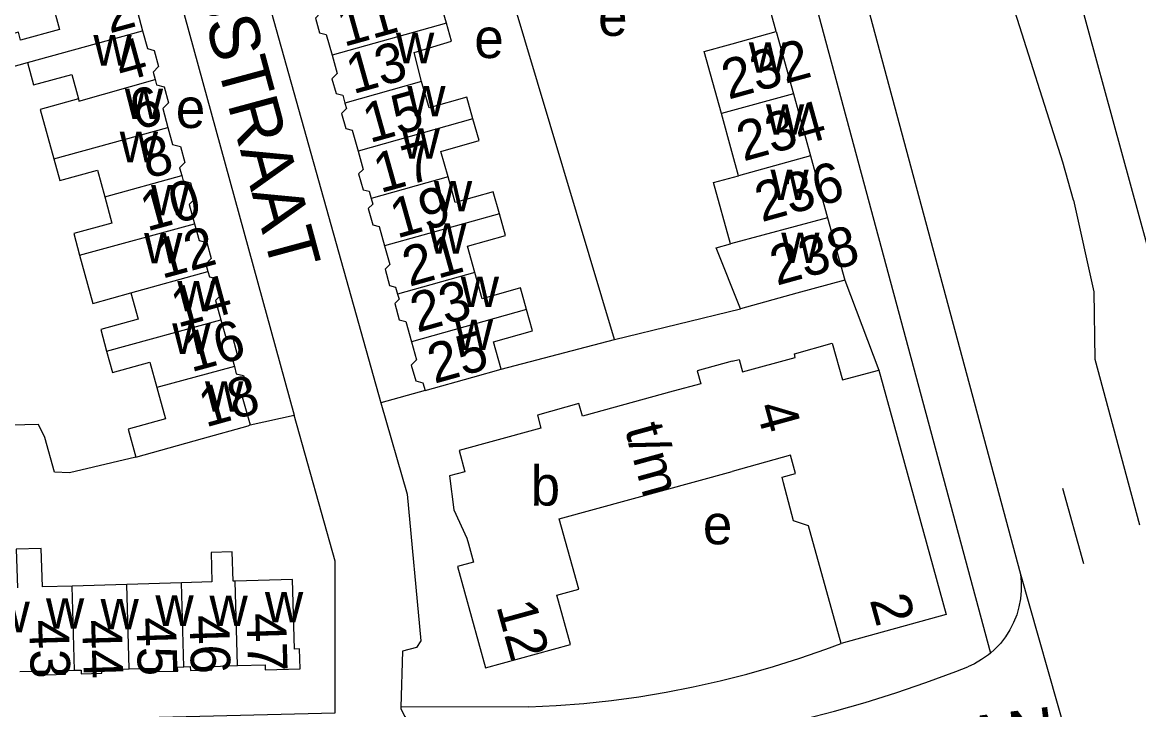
# Model space of a CAD drawing. Extents: x 161258 to 163262, y 380749 to 382054.
# Drawn here: x 162428.3 to 162541.1, y 381217.9 to 381287.2 of the extents above; entities that cross this region are included whole.
import ezdxf

# ---------------------------------------------------------------- set-up
doc = ezdxf.new("R2010")
doc.units = 0
for name, color, linetype in [('BLT_Basislijn', 7, 'Continuous'), ('BLT_Bebouwing', 7, 'Continuous'), ('BLT_Centroide', 7, 'Continuous'), ('BLT_Huisnummer', 7, 'Continuous'), ('BLT_Huisnummer_ tussenligend', 7, 'Continuous'), ('BLT_Huisnummer_reeks', 7, 'Continuous'), ('BLT_Onderverdeling_panden', 7, 'Continuous'), ('BLT_Straatnaam', 7, 'Continuous'), ('BLT_Vlakafsluiter', 7, 'Continuous')]:
    doc.layers.add(name, color=color, linetype=linetype)

msp = doc.modelspace()

# ---------------------------------------------------------------- linework, layer by layer
at = {"layer": 'BLT_Basislijn'}
for p, q in [((162533.38, 381273.13), (162520.81, 381312.73)), ((162488.11, 381255.23), (162472.07, 381308.92)), ((162440.6, 381302.96), (162455.78, 381247.6)), ((162510.03, 381302.47), (162529.11, 381231.56)), ((162505.17, 381301.27), (162526.08, 381223.58)), ((162504.46, 381286.31), (162503, 381291.56)), ((162534.49, 381269.29), (162533.38, 381273.13)), ((162511.37, 381261.23), (162514.81, 381252.15)), ((162488.11, 381255.23), (162500.86, 381258.34)), ((162476.68, 381252.24), (162488.11, 381255.23)), ((162469, 381250.08), (162464.52, 381248.83)), ((162451.33, 381246.61), (162455.78, 381247.6)), ((162533.36, 381240.23), (162535.48, 381232.62)), ((162466.56, 381218.13), (162466.55, 381217.95)), ((162479.46, 381218.15), (162466.56, 381218.13))]:
    msp.add_line(p, q, dxfattribs=at)
for points in [[(162449.41, 381302.85), (162449.7, 381301.79), (162464.52, 381248.83)], [(162534.49, 381269.29), (162536.54, 381260.03), (162536.62, 381253.26), (162541.13, 381236.52)], [(162464.52, 381248.83), (162467.18, 381239.63), (162468.56, 381224.8)], [(162377.35, 381241.55), (162374.93, 381229.15), (162375.77, 381216.02), (162376.51, 381215.48), (162459.91, 381217.55), (162459.91, 381232.85), (162455.78, 381247.6)], [(162439.81, 381243.36), (162433.08, 381241.77), (162431.59, 381241.85), (162430.62, 381245.34), (162429.95, 381246.65), (162408.03, 381246.1)], [(162529.11, 381231.56), (162529.2, 381230.73), (162529.2, 381229.9), (162529.13, 381229.06), (162528.97, 381228.24), (162528.74, 381227.44), (162528.43, 381226.66), (162528.05, 381225.92), (162527.6, 381225.21), (162527.09, 381224.56), (162526.51, 381223.95), (162526.08, 381223.58)], [(162468.56, 381224.8), (162468.14, 381224.14), (162466.73, 381223.78), (162466.56, 381218.13)], [(162479.46, 381218.15), (162482.25, 381218.29), (162485.04, 381218.5), (162487.81, 381218.8), (162490.58, 381219.17), (162493.33, 381219.62), (162496.07, 381220.16), (162498.79, 381220.77), (162501.5, 381221.46), (162504.18, 381222.22), (162506.84, 381223.06), (162509.48, 381223.98), (162511, 381224.55)], [(162526.08, 381223.58), (162525.88, 381223.4), (162525.2, 381222.92), (162524.47, 381222.5), (162523.81, 381222.19)], [(162472.03, 381213.18), (162475.26, 381213.11), (162478.48, 381213.14), (162481.71, 381213.24), (162484.93, 381213.42), (162488.15, 381213.68), (162491.35, 381214.02), (162494.55, 381214.43), (162497.74, 381214.93), (162500.92, 381215.51), (162504.07, 381216.17), (162507.22, 381216.9), (162510.34, 381217.71), (162513.44, 381218.6), (162516.52, 381219.56), (162519.57, 381220.61), (162522.6, 381221.72), (162523.81, 381222.19)], [(162466.55, 381217.95), (162466.97, 381217.19), (162467.45, 381216.47), (162468, 381215.8), (162468.61, 381215.19), (162469.27, 381214.63), (162469.98, 381214.14), (162470.74, 381213.71), (162471.53, 381213.36), (162472.03, 381213.18)]]:
    msp.add_lwpolyline(points, dxfattribs=at)
at = {"layer": 'BLT_Bebouwing'}
for p, q in [((162530.18, 381307.51), (162544.19, 381256.3)), ((162500, 381285.08), (162504.46, 381286.31)), ((162504.46, 381286.31), (162506.19, 381280.04)), ((162506.19, 381280.04), (162507.91, 381273.78)), ((162499.99, 381274.19), (162498.92, 381278.03)), ((162500.66, 381271.76), (162499.99, 381274.19)), ((162507.91, 381273.78), (162509.64, 381267.51)), ((162509.64, 381267.51), (162511.37, 381261.23)), ((162514.81, 381252.15), (162516.39, 381246.43)), ((162505.89, 381243.54), (162500, 381241.92)), ((162482.55, 381237.12), (162500, 381241.92)), ((162438.88, 381230.51), (162433.35, 381230.35)), ((162444.4, 381230.68), (162438.88, 381230.51))]:
    msp.add_line(p, q, dxfattribs=at)
for points in [[(162439.02, 381291.45), (162439.24, 381290.63), (162440.01, 381290.43), (162440.45, 381288.81), (162439.95, 381288.3), (162440.47, 381286.37)], [(162471.15, 381287.17), (162470.53, 381289.36), (162466.7, 381288.28), (162465.97, 381290.88)], [(162431.32, 381289.35), (162432.09, 381286.51), (162428.15, 381285.44), (162427.93, 381286.24), (162424.39, 381285.28), (162425.23, 381282.19), (162428.86, 381283.2)], [(162458.25, 381288.72), (162458.4, 381288.16), (162457.92, 381287.67), (162458.34, 381286.19), (162459.02, 381286.01), (162459.61, 381283.94)], [(162468.65, 381281.27), (162467.9, 381284.2), (162471.67, 381285.33), (162471.15, 381287.17)], [(162440.47, 381286.37), (162440.96, 381284.59), (162441.64, 381284.41), (162442.09, 381282.79), (162441.53, 381282.23), (162441.74, 381281.47)], [(162498.92, 381278.03), (162497.17, 381284.29), (162499.64, 381284.98), (162500, 381285.08)], [(162459.61, 381283.94), (162460.13, 381282.08), (162459.6, 381281.53), (162460.02, 381280.05), (162460.69, 381279.88), (162460.91, 381279.09)], [(162428.86, 381283.2), (162429.47, 381280.94), (162433.32, 381281.99), (162433.99, 381279.51)], [(162441.74, 381281.47), (162441.88, 381280.93), (162442.65, 381280.73), (162443.09, 381279.11), (162442.52, 381278.53), (162443.04, 381276.63)], [(162473.83, 381277.5), (162473.22, 381279.69), (162469.4, 381278.62), (162468.65, 381281.27)], [(162433.99, 381279.51), (162430.15, 381278.46), (162431.51, 381273.48)], [(162460.91, 381279.09), (162461.06, 381278.54), (162460.56, 381278.03), (162460.99, 381276.53), (162461.64, 381276.36), (162462.23, 381274.24)], [(162443.04, 381276.63), (162443.51, 381274.91), (162444.3, 381274.7), (162444.74, 381273.09), (162444.21, 381272.56), (162444.43, 381271.77)], [(162471.33, 381271.64), (162470.6, 381274.22), (162474.45, 381275.3), (162473.83, 381277.5)], [(162431.51, 381273.48), (162432.11, 381271.27), (162435.93, 381272.31), (162436.65, 381269.64)], [(162462.23, 381274.24), (162462.75, 381272.4), (162462.29, 381271.94), (162462.74, 381270.35), (162463.34, 381270.19), (162463.55, 381269.45)], [(162444.43, 381271.77), (162444.57, 381271.24), (162445.3, 381271.05), (162445.75, 381269.42), (162445.19, 381268.85), (162445.71, 381266.92)], [(162476.51, 381267.93), (162475.89, 381270.13), (162472.05, 381269.05), (162471.33, 381271.64)], [(162499.83, 381264.88), (162498.12, 381271.07), (162500.66, 381271.76)], [(162436.65, 381269.64), (162437.38, 381266.97), (162433.53, 381265.92), (162434.12, 381263.75)], [(162463.55, 381269.45), (162463.71, 381268.89), (162463.27, 381268.44), (162463.74, 381266.79), (162464.36, 381266.63), (162464.91, 381264.68)], [(162474.01, 381262), (162473.27, 381264.65), (162477.12, 381265.73), (162476.51, 381267.93)], [(162445.71, 381266.92), (162446.18, 381265.22), (162446.96, 381265.02), (162447.4, 381263.39), (162446.87, 381262.85), (162447.08, 381262.08)], [(162464.91, 381264.68), (162465.44, 381262.81), (162464.96, 381262.32), (162465.42, 381260.67), (162466.03, 381260.52), (162466.22, 381259.81)], [(162500.86, 381258.34), (162498.39, 381264.48), (162499.83, 381264.88)], [(162434.12, 381263.75), (162435.45, 381258.87), (162439.3, 381259.95)], [(162447.08, 381262.08), (162447.22, 381261.55), (162447.96, 381261.36), (162448.4, 381259.74), (162447.85, 381259.18), (162448.38, 381257.22)], [(162479.24, 381258.27), (162478.63, 381260.43), (162474.76, 381259.35), (162474.01, 381262)], [(162511.37, 381261.23), (162506.55, 381259.9), (162500.86, 381258.34)], [(162439.3, 381259.95), (162440.03, 381257.27), (162436.25, 381256.24), (162436.84, 381254.07)], [(162466.22, 381259.81), (162466.37, 381259.3), (162465.93, 381258.86), (162466.39, 381257.21), (162467.05, 381257.04), (162467.62, 381255)], [(162476.68, 381252.24), (162475.91, 381254.99), (162479.84, 381256.1), (162479.24, 381258.27)], [(162448.38, 381257.22), (162448.84, 381255.56), (162449.59, 381255.36), (162450.04, 381253.73), (162449.54, 381253.22), (162449.74, 381252.5)], [(162436.84, 381254.07), (162437.43, 381251.9), (162441.22, 381252.94), (162441.93, 381250.37)], [(162467.62, 381255), (162468.13, 381253.18), (162467.61, 381252.65), (162468.06, 381251.05), (162468.77, 381250.87), (162469, 381250.08)], [(162500, 381253.03), (162500.7, 381253.22), (162501.04, 381251.96), (162506.38, 381253.43), (162506.29, 381253.79), (162510.12, 381254.85), (162511.14, 381251.15)], [(162500, 381253.03), (162496.48, 381252.06), (162496.83, 381250.76), (162494.05, 381250), (162484.88, 381247.48), (162484.52, 381248.76), (162480.34, 381247.61), (162480.7, 381246.29), (162479.95, 381246.09)], [(162449.74, 381252.5), (162449.93, 381251.78), (162450.65, 381251.59), (162451.09, 381250), (162450.54, 381249.43), (162451.33, 381246.61)], [(162469, 381250.08), (162473.81, 381251.43), (162476.68, 381252.24)], [(162511.14, 381251.15), (162514.81, 381252.15)], [(162441.93, 381250.37), (162442.03, 381250), (162442.8, 381247.22), (162439.03, 381246.17), (162439.81, 381243.36)], [(162439.81, 381243.36), (162446.52, 381245.23), (162451.12, 381246.51), (162451.33, 381246.61)], [(162516.39, 381246.43), (162521.6, 381227.48), (162511, 381224.55)], [(162479.95, 381246.09), (162472.43, 381244.02), (162473.02, 381241.89), (162471.45, 381241.46), (162471.91, 381238.05), (162473.21, 381235.17), (162473.37, 381234.59)], [(162505.2, 381240.76), (162505.04, 381241.35), (162506.39, 381241.72), (162505.89, 381243.54)], [(162511, 381224.55), (162507.73, 381236.41), (162506.2, 381236.94), (162505.2, 381240.76)], [(162473.37, 381234.59), (162473.88, 381232.75), (162472.29, 381232.32), (162475.11, 381222.09), (162483.69, 381224.46), (162482.32, 381229.42), (162484.51, 381230.02), (162482.55, 381237.12)], [(162433.35, 381230.35), (162430.36, 381230.26), (162430.25, 381234.15), (162427.71, 381234.07), (162427.83, 381230.18)], [(162449.82, 381230.84), (162449.61, 381230.84), (162449.52, 381233.8), (162447.39, 381233.73), (162447.48, 381230.77), (162444.4, 381230.68)], [(162450.06, 381222.32), (162452.84, 381222.4), (162452.86, 381221.89), (162456.39, 381222), (162456.33, 381224.01), (162455.81, 381223.99), (162455.6, 381231.02), (162449.82, 381230.84)], [(162428.08, 381221.72), (162430.81, 381221.8), (162430.82, 381221.39), (162432.7, 381221.45), (162432.69, 381221.83), (162433.6, 381221.85)], [(162433.6, 381221.85), (162434.26, 381221.87), (162434.27, 381221.49), (162436.37, 381221.55), (162436.36, 381221.91), (162439.12, 381221.99)], [(162439.12, 381221.99), (162441.89, 381222.07), (162441.9, 381221.71), (162444.02, 381221.77), (162444.01, 381222.17), (162444.64, 381222.19)], [(162444.64, 381222.19), (162445.29, 381222.21), (162445.3, 381221.83), (162447.47, 381221.9), (162447.46, 381222.24), (162450.06, 381222.32)]]:
    msp.add_lwpolyline(points, dxfattribs=at)
at = {"layer": 'BLT_Onderverdeling_panden'}
for p, q in [((162471.15, 381287.17), (162459.61, 381283.94)), ((162428.86, 381283.2), (162440.47, 381286.37)), ((162468.65, 381281.27), (162460.91, 381279.09)), ((162506.19, 381280.04), (162498.92, 381278.03)), ((162431.51, 381273.48), (162443.04, 381276.63)), ((162473.83, 381277.5), (162462.23, 381274.24)), ((162507.91, 381273.78), (162500.66, 381271.76)), ((162436.65, 381269.64), (162444.43, 381271.77)), ((162471.33, 381271.64), (162463.55, 381269.45)), ((162476.51, 381267.93), (162464.91, 381264.68)), ((162434.12, 381263.75), (162445.71, 381266.92)), ((162509.64, 381267.51), (162499.83, 381264.88)), ((162439.3, 381259.95), (162447.08, 381262.08)), ((162474.01, 381262), (162466.22, 381259.81)), ((162479.24, 381258.27), (162467.62, 381255)), ((162436.84, 381254.07), (162448.38, 381257.22)), ((162449.74, 381252.5), (162441.93, 381250.37)), ((162433.6, 381221.85), (162433.35, 381230.35)), ((162439.12, 381221.99), (162438.88, 381230.51)), ((162444.64, 381222.19), (162444.4, 381230.68)), ((162450.06, 381222.32), (162449.82, 381230.84))]:
    msp.add_line(p, q, dxfattribs=at)
msp.add_lwpolyline([(162433.99, 381279.51), (162434.05, 381279.28), (162441.74, 381281.47)], dxfattribs=at)
at = {"layer": 'BLT_Vlakafsluiter'}
msp.add_line((162529.11, 381231.56), (162536.54, 381205.57), dxfattribs=at)

# ---------------------------------------------------------------- texts
at = {"layer": 'BLT_Centroide'}
for s, p in [('e', (162486.47, 381285.88)), ('e', (162473.97, 381283.64)), ('w', (162435.51, 381282.88)), ('w', (162466.06, 381283.12)), ('w', (162501.69, 381282.16)), ('w', (162438.68, 381277.47)), ('w', (162467.2, 381277.75)), ('e', (162443.83, 381276.58)), ('w', (162503.42, 381275.91)), ('w', (162466.63, 381273.47)), ('w', (162438.17, 381273.12)), ('w', (162503.87, 381269.31)), ('w', (162469.89, 381268.16)), ('w', (162441.33, 381267.75)), ('w', (162469.31, 381263.88)), ('w', (162440.63, 381262.91)), ('w', (162504.96, 381262.94)), ('w', (162443.98, 381258.06)), ('w', (162472.6, 381258.5)), ('w', (162443.47, 381253.78)), ('w', (162472, 381254.16)), ('w', (162446.78, 381247.94)), ('b', (162479.66, 381238.47)), ('e', (162497.05, 381234.56)), ('w', (162441.77, 381226.33)), ('w', (162447.23, 381226.31)), ('w', (162452.83, 381226.67)), ('w', (162425.22, 381225.69)), ('w', (162430.72, 381226.05)), ('w', (162436.23, 381225.98))]:
    msp.add_text(s, height=4, dxfattribs=at).set_placement(p)
at = {"layer": 'BLT_Huisnummer'}
for s, rotation, p in [('2', 15.2732, (162437.14, 381286.11)), ('11', 15.6623, (162460.79, 381284.75)), ('232', 15.5009, (162499.62, 381279.43)), ('6', 15.2749, (162439.86, 381276.34)), ('15', 15.6822, (162463.4, 381275.04)), ('10', 15.2656, (162440.91, 381266.12)), ('19', 15.6726, (162466.15, 381265.41)), ('238', 15.4149, (162504.5, 381260.65)), ('14', 15.2652, (162444.01, 381256.41)), ('25', 15.6731, (162469.93, 381250.75)), ('18', 15.5597, (162446.83, 381246.34)), ('45', 271.6504, (162439.84, 381227.16)), ('46', 271.6491, (162445.2, 381227.37)), ('47', 271.7133, (162450.95, 381227.59)), ('43', 271.6528, (162429.02, 381226.9)), ('44', 271.6516, (162434.37, 381226.9))]:
    msp.add_text(s, height=4, rotation=rotation, dxfattribs=at).set_placement(p)
at = {"layer": 'BLT_Huisnummer_ tussenligend'}
for s, rotation, p in [('4', 15.2732, (162438.35, 381281.19)), ('13', 15.6623, (162461.72, 381279.98)), ('234', 15.5009, (162501.14, 381273.19)), ('8', 15.2749, (162440.96, 381271.43)), ('17', 15.6822, (162464.48, 381269.99)), ('236', 15.5009, (162502.98, 381267.06)), ('12', 15.2656, (162442.42, 381261.34)), ('21', 15.6726, (162467.4, 381260.54)), ('23', 15.6726, (162468.2, 381255.91)), ('16', 15.2652, (162445.37, 381251.91))]:
    msp.add_text(s, height=4, rotation=rotation, dxfattribs=at).set_placement(p)
at = {"layer": 'BLT_Huisnummer_reeks'}
for s, rotation, p in [('4', 285.3926, (162502.36, 381248.43)), ('t/m', 285.3926, (162489.15, 381246.21)), ('2', 285.4304, (162513.88, 381228.95)), ('12', 285.3926, (162476.17, 381228.33))]:
    msp.add_text(s, height=4, rotation=rotation, dxfattribs=at).set_placement(p)
at = {"layer": 'BLT_Straatnaam'}
for s, height, rotation, p in [('STOKROOSSTRAAT', 4.9999, 285.1334, (162436.91, 381323.86)), ('KERSTROOSLAAN', 5, 7.2093, (162474.01, 381205.79))]:
    msp.add_text(s, height=height, rotation=rotation, dxfattribs=at).set_placement(p)

doc.saveas('drawing.dxf')
